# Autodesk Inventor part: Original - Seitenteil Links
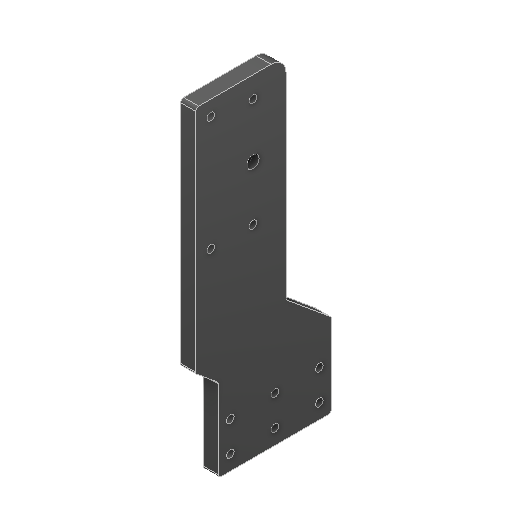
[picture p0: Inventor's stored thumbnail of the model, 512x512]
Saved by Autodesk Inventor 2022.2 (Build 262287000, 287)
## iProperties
Created: 2024-09
Part Number: Original - Seitenteil Links
Material: Generico
Document SubType Name: Modeling
Designer: 18907419
Density: 1 g/cm^3
Appearance: Default
Author: 18907419
Revision Number: ANY
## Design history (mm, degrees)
feature "Schnitt-Linear austragen2"
node "Solido1"
